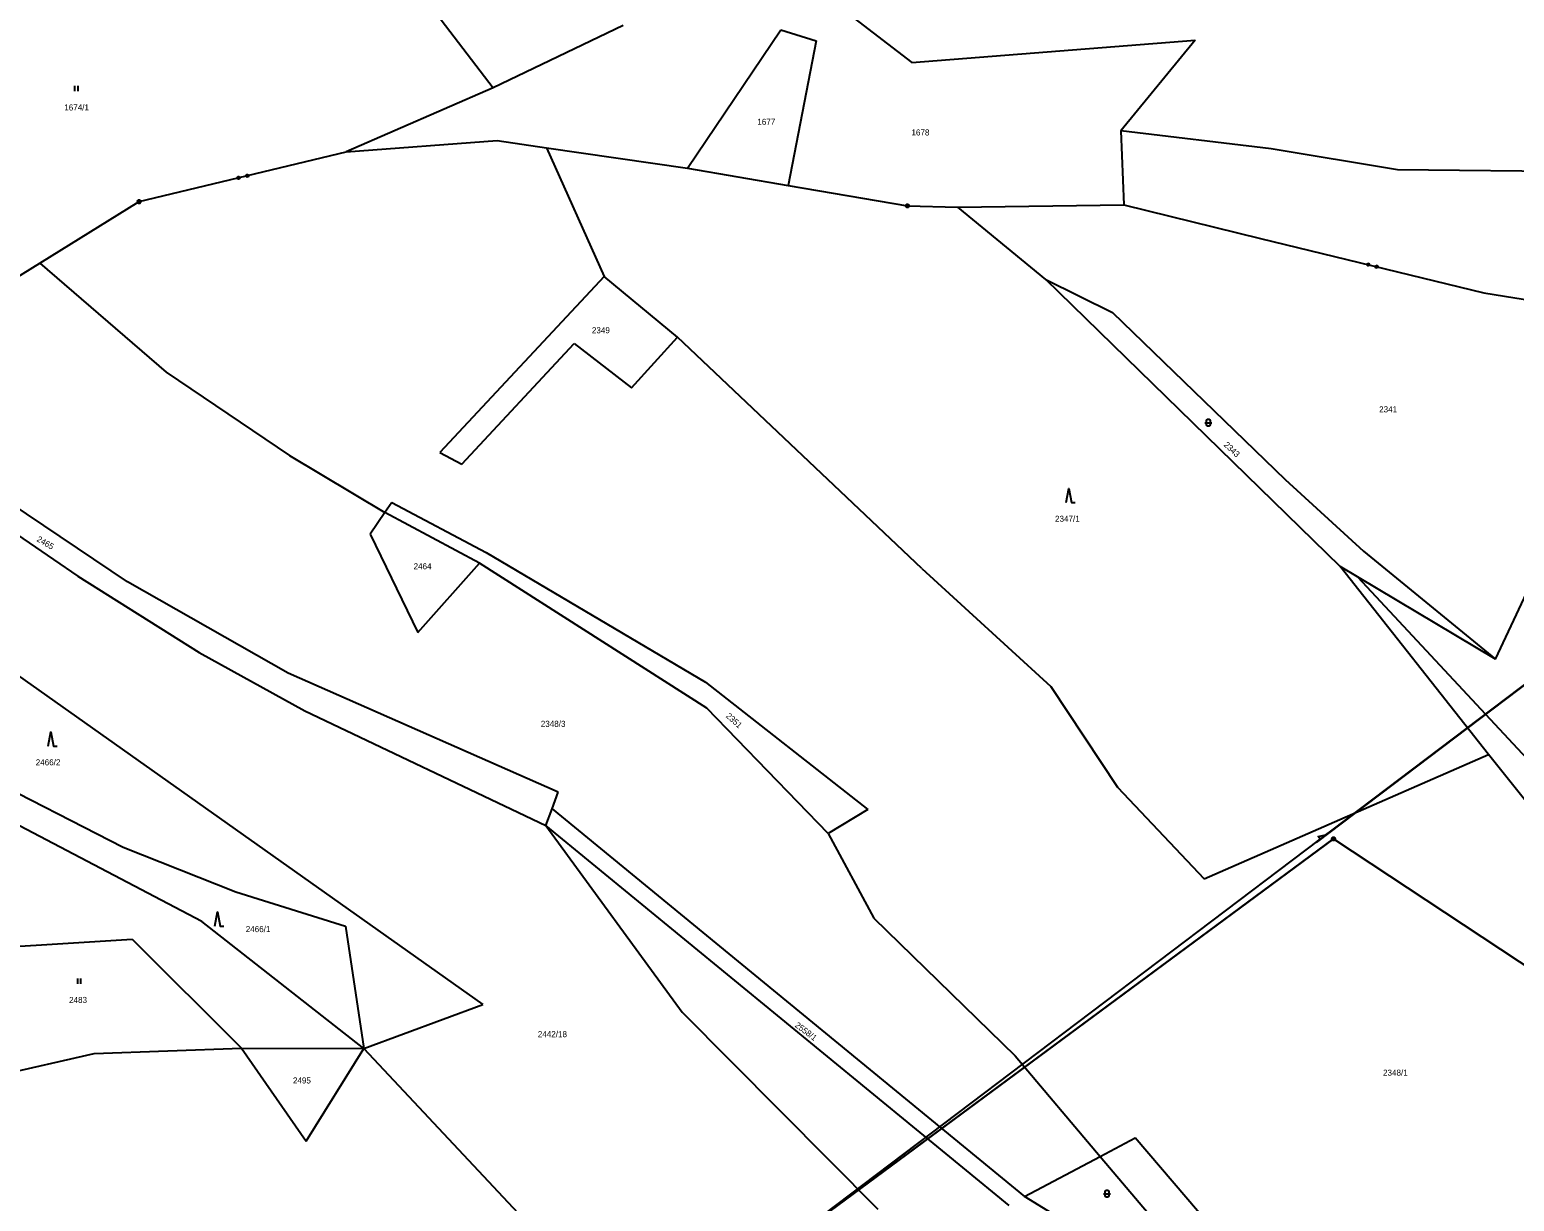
# Model space of a CAD drawing. Extents: x -747792 to -745414, y -1093712 to -1091463.
# Drawn here: x -747200 to -746990.9, y -1092601.7 to -1092436.7 of the extents above; entities that cross this region are included whole.
import ezdxf

# ---------------------------------------------------------------- set-up
doc = ezdxf.new("R2010")
doc.units = 0
for name, color, linetype in [('Pracovní_bod JDTM STC_VC', 7, 'Continuous'), ('Pracovní_bod JDTM STC_VC - číslo', 7, 'Continuous'), ('Pracovní_bod NN - výška', 7, 'Continuous'), ('Pracovní_bod polohopisu - číslo', 7, 'Continuous'), ('Pracovní_bod VN - výška', 7, 'Continuous')]:
    doc.layers.add(name, color=color, linetype=linetype)

msp = doc.modelspace()

# ---------------------------------------------------------------- linework, layer by layer
at = {"layer": 'Pracovní_bod JDTM STC_VC - číslo'}
for points in [[(-747193.73, -1092444.63), (-747193.73, -1092445.38)], [(-747193.23, -1092445.38), (-747193.23, -1092444.63)], [(-747034.52, -1092492.05), (-747033.89, -1092492.05), (-747033.52, -1092492.05)], [(-747054.05, -1092503.3), (-747053.67, -1092501.3), (-747053.3, -1092503.3), (-747052.8, -1092503.3)], [(-747197.44, -1092537.6), (-747197.06, -1092535.6), (-747196.69, -1092537.6), (-747196.19, -1092537.6)], [(-747173.96, -1092562.94), (-747173.59, -1092560.94), (-747173.21, -1092562.94), (-747172.71, -1092562.94)], [(-747193.32, -1092570.31), (-747193.32, -1092571.06)], [(-747192.82, -1092571.06), (-747192.82, -1092570.31)], [(-747048.81, -1092600.62), (-747048.18, -1092600.62), (-747047.81, -1092600.62)]]:
    msp.add_lwpolyline(points, dxfattribs=at)
for points in [[(-747034.27, -1092491.8), (-747034.22, -1092491.66), (-747034.09, -1092491.56), (-747033.94, -1092491.56), (-747033.82, -1092491.66), (-747033.77, -1092491.8), (-747033.77, -1092492.3), (-747033.82, -1092492.45), (-747033.94, -1092492.54), (-747034.09, -1092492.54), (-747034.22, -1092492.45), (-747034.27, -1092492.3)], [(-747048.56, -1092600.37), (-747048.51, -1092600.23), (-747048.39, -1092600.14), (-747048.23, -1092600.14), (-747048.1, -1092600.23), (-747048.06, -1092600.37), (-747048.06, -1092600.87), (-747048.1, -1092601.02), (-747048.23, -1092601.1), (-747048.39, -1092601.1), (-747048.51, -1092601.02), (-747048.56, -1092600.87)]]:
    msp.add_lwpolyline(points, close=True, dxfattribs=at)
at = {"layer": 'Pracovní_bod NN - výška'}
for points in [[(-747095.57, -1092426.1), (-747075.77, -1092441.31)], [(-747146.95, -1092428.88), (-747134.78, -1092444.91)], [(-747116.43, -1092436.11), (-747134.78, -1092444.91)], [(-747107.37, -1092456.22), (-747094.26, -1092436.73)], [(-747094.26, -1092436.73), (-747089.27, -1092438.27)], [(-747089.27, -1092438.27), (-747093.21, -1092458.64)], [(-747075.77, -1092441.31), (-747035.87, -1092438.2)], [(-747035.87, -1092438.2), (-747046.34, -1092450.93)], [(-747134.78, -1092444.91), (-747155.44, -1092453.91)], [(-747046.34, -1092450.93), (-747045.92, -1092461.39)], [(-747025.2, -1092453.5), (-747046.34, -1092450.93)], [(-747155.44, -1092453.91), (-747134.18, -1092452.33)], [(-747134.18, -1092452.33), (-747127.25, -1092453.33)], [(-747127.25, -1092453.33), (-747107.37, -1092456.22)], [(-747127.25, -1092453.33), (-747119.14, -1092471.47)], [(-747007.36, -1092456.44), (-747025.2, -1092453.5)], [(-747184.61, -1092460.92), (-747155.44, -1092453.91)], [(-747170.58, -1092457.38), (-747170.47, -1092457.45), (-747170.44, -1092457.59), (-747170.51, -1092457.7), (-747170.64, -1092457.73), (-747170.75, -1092457.66), (-747170.78, -1092457.53), (-747170.71, -1092457.42), (-747170.58, -1092457.38), (-747170.58, -1092457.41), (-747170.7, -1092457.43), (-747170.73, -1092457.48), (-747170.53, -1092457.43), (-747170.49, -1092457.46), (-747170.76, -1092457.53), (-747170.75, -1092457.57), (-747170.48, -1092457.5), (-747170.47, -1092457.54), (-747170.74, -1092457.61), (-747170.73, -1092457.65), (-747170.46, -1092457.58), (-747170.49, -1092457.63), (-747170.68, -1092457.68), (-747170.63, -1092457.71), (-747170.52, -1092457.68)], [(-747169.37, -1092457.09), (-747169.25, -1092457.16), (-747169.22, -1092457.29), (-747169.29, -1092457.41), (-747169.42, -1092457.44), (-747169.54, -1092457.37), (-747169.57, -1092457.24), (-747169.5, -1092457.12), (-747169.37, -1092457.09), (-747169.38, -1092457.12), (-747169.49, -1092457.14), (-747169.52, -1092457.19), (-747169.33, -1092457.14), (-747169.28, -1092457.17), (-747169.55, -1092457.24), (-747169.54, -1092457.28), (-747169.27, -1092457.21), (-747169.26, -1092457.25), (-747169.53, -1092457.32), (-747169.52, -1092457.36), (-747169.25, -1092457.29), (-747169.28, -1092457.34), (-747169.48, -1092457.39), (-747169.43, -1092457.42), (-747169.31, -1092457.39)], [(-747107.37, -1092456.22), (-747093.21, -1092458.64)], [(-746981.14, -1092456.74), (-747007.36, -1092456.44)], [(-747093.21, -1092458.64), (-747076.39, -1092461.51)], [(-747198.62, -1092469.58), (-747184.61, -1092460.92)], [(-747076.39, -1092461.51), (-747069.3, -1092461.71)], [(-747069.3, -1092461.71), (-747045.92, -1092461.39)], [(-747056.93, -1092471.88), (-747069.3, -1092461.71)], [(-747045.92, -1092461.39), (-747026.66, -1092466.11)], [(-747026.66, -1092466.11), (-746995.22, -1092473.74)], [(-747210.01, -1092476.61), (-747198.62, -1092469.58)], [(-747198.62, -1092469.58), (-747180.81, -1092484.94)], [(-747011.42, -1092469.64), (-747011.35, -1092469.76), (-747011.38, -1092469.89), (-747011.5, -1092469.96), (-747011.63, -1092469.93), (-747011.7, -1092469.81), (-747011.67, -1092469.68), (-747011.55, -1092469.61), (-747011.42, -1092469.64), (-747011.43, -1092469.66), (-747011.55, -1092469.63), (-747011.6, -1092469.66), (-747011.4, -1092469.71), (-747011.37, -1092469.76), (-747011.64, -1092469.69), (-747011.65, -1092469.73), (-747011.38, -1092469.8), (-747011.39, -1092469.84), (-747011.66, -1092469.77), (-747011.67, -1092469.81), (-747011.4, -1092469.87), (-747011.45, -1092469.9), (-747011.64, -1092469.86), (-747011.61, -1092469.91), (-747011.5, -1092469.93)], [(-747010.21, -1092469.94), (-747010.14, -1092470.05), (-747010.17, -1092470.18), (-747010.28, -1092470.25), (-747010.42, -1092470.22), (-747010.49, -1092470.11), (-747010.45, -1092469.98), (-747010.34, -1092469.91), (-747010.21, -1092469.94), (-747010.23, -1092469.95), (-747010.34, -1092469.93), (-747010.39, -1092469.96), (-747010.2, -1092470), (-747010.17, -1092470.05), (-747010.44, -1092469.98), (-747010.45, -1092470.02), (-747010.18, -1092470.09), (-747010.19, -1092470.13), (-747010.46, -1092470.06), (-747010.47, -1092470.1), (-747010.2, -1092470.17), (-747010.24, -1092470.2), (-747010.44, -1092470.15), (-747010.41, -1092470.2), (-747010.29, -1092470.23)], [(-747119.14, -1092471.47), (-747142.29, -1092496.25)], [(-747108.8, -1092480.02), (-747119.14, -1092471.47)], [(-747015.48, -1092512.3), (-747056.93, -1092471.88)], [(-747056.93, -1092471.88), (-747047.53, -1092476.51)], [(-746995.22, -1092473.74), (-746972.76, -1092477.36)], [(-747047.53, -1092476.51), (-747023.2, -1092500.06)], [(-747115.28, -1092487.14), (-747108.8, -1092480.02)], [(-747074.38, -1092512.56), (-747108.8, -1092480.02)], [(-747139.19, -1092497.89), (-747123.35, -1092480.89)], [(-747123.35, -1092480.89), (-747115.28, -1092487.14)], [(-747180.81, -1092484.94), (-747163.45, -1092496.66)], [(-747186.27, -1092514.47), (-747226.54, -1092487.36)], [(-747163.45, -1092496.66), (-747150.01, -1092504.69)], [(-747142.29, -1092496.25), (-747139.19, -1092497.89)], [(-746993.57, -1092525.37), (-746979.63, -1092495.68)], [(-747023.2, -1092500.06), (-747012.15, -1092510.12)], [(-747149.04, -1092503.27), (-747150.01, -1092504.69)], [(-747149.04, -1092503.27), (-747135.76, -1092510.35)], [(-747207, -1092504.27), (-747193.26, -1092513.66)], [(-747150.01, -1092504.69), (-747152.09, -1092507.75)], [(-747136.68, -1092511.85), (-747150.01, -1092504.69)], [(-747152.09, -1092507.75), (-747145.38, -1092521.61)], [(-747145.38, -1092521.61), (-747136.68, -1092511.85)], [(-747104.64, -1092532.25), (-747136.68, -1092511.85)], [(-747135.76, -1092510.35), (-747104.83, -1092528.6)], [(-747012.15, -1092510.12), (-746993.57, -1092525.37)], [(-747193.26, -1092513.66), (-747176.16, -1092524.41)], [(-747074.38, -1092512.56), (-747056.22, -1092529.19)], [(-746994.58, -1092538.79), (-747015.48, -1092512.3)], [(-747013.03, -1092513.76), (-747015.48, -1092512.3)], [(-747013.03, -1092513.76), (-746951.86, -1092579.36)], [(-746993.57, -1092525.37), (-747013.03, -1092513.76)], [(-747163.63, -1092527.3), (-747186.27, -1092514.47)], [(-747207.15, -1092523.79), (-747136.22, -1092573.97)], [(-747176.16, -1092524.41), (-747161.29, -1092532.62)], [(-747175.77, -1092562.31), (-747239.54, -1092528.86)], [(-747125.62, -1092544.1), (-747163.63, -1092527.3)], [(-747104.83, -1092528.6), (-747081.99, -1092546.51)], [(-747056.22, -1092529.19), (-747046.81, -1092543.35)], [(-747161.29, -1092532.62), (-747127.32, -1092548.77)], [(-747087.55, -1092549.91), (-747104.64, -1092532.25)], [(-747034.63, -1092556.29), (-746994.58, -1092538.79)], [(-746969.61, -1092570), (-746994.58, -1092538.79)], [(-747207.26, -1092541.38), (-747186.89, -1092551.84)], [(-747046.81, -1092543.35), (-747034.63, -1092556.29)], [(-747126.46, -1092546.42), (-747125.62, -1092544.1)], [(-747127.32, -1092548.77), (-747126.46, -1092546.42)], [(-747126.46, -1092546.42), (-747059.94, -1092601.01)], [(-747081.99, -1092546.51), (-747087.55, -1092549.91)], [(-747127.32, -1092548.77), (-747108.12, -1092575.08)], [(-747062.09, -1092602.28), (-747127.32, -1092548.77)], [(-747186.89, -1092551.84), (-747170.99, -1092558.13)], [(-747087.55, -1092549.91), (-747081.13, -1092561.8)], [(-747170.99, -1092558.13), (-747155.58, -1092562.96)], [(-747152.98, -1092580.18), (-747175.77, -1092562.31)], [(-747081.13, -1092561.8), (-747061.22, -1092581.21)], [(-747155.58, -1092562.96), (-747152.98, -1092580.18)], [(-747213.49, -1092566.53), (-747185.62, -1092564.79)], [(-747185.62, -1092564.79), (-747170.21, -1092580.13)], [(-747152.98, -1092580.18), (-747136.22, -1092573.97)], [(-747108.12, -1092575.08), (-747080.59, -1092602.79)], [(-747204.55, -1092583.99), (-747190.94, -1092580.88)], [(-747190.94, -1092580.88), (-747170.21, -1092580.13)], [(-747170.21, -1092580.13), (-747161.12, -1092593.23)], [(-747170.21, -1092580.13), (-747152.98, -1092580.18)], [(-747161.12, -1092593.23), (-747152.98, -1092580.18)], [(-747152.98, -1092580.18), (-747125.63, -1092609.32)], [(-747061.22, -1092581.21), (-747049.25, -1092595.36)], [(-747049.25, -1092595.36), (-747044.33, -1092592.76)], [(-747026.5, -1092613.63), (-747044.33, -1092592.76)], [(-747059.94, -1092601.01), (-747049.25, -1092595.36)], [(-747049.25, -1092595.36), (-747028.84, -1092619.47)], [(-747027.96, -1092620.69), (-747059.94, -1092601.01)]]:
    msp.add_lwpolyline(points, dxfattribs=at)
at = {"layer": 'Pracovní_bod polohopisu - číslo'}
for points in [[(-747097.67, -1092610.73), (-746937.26, -1092489.46), (-747018.86, -1092551.15)], [(-747018.66, -1092551), (-747018.27, -1092550.7), (-747018.57, -1092550.3), (-747017.47, -1092550.1), (-747016.27, -1092549.19)], [(-747181.77, -1092672.87), (-747016.39, -1092550.67), (-747100.49, -1092612.81)], [(-747016.47, -1092550.43), (-747016.31, -1092550.43), (-747016.19, -1092550.52), (-747016.14, -1092550.67), (-747016.19, -1092550.81), (-747016.31, -1092550.9), (-747016.47, -1092550.9), (-747016.59, -1092550.81), (-747016.64, -1092550.67), (-747016.59, -1092550.52), (-747016.47, -1092550.43), (-747016.45, -1092550.45), (-747016.33, -1092550.45), (-747016.25, -1092550.49), (-747016.53, -1092550.49), (-747016.57, -1092550.53), (-747016.21, -1092550.53), (-747016.21, -1092550.57), (-747016.57, -1092550.57), (-747016.59, -1092550.61), (-747016.19, -1092550.61), (-747016.17, -1092550.65), (-747016.61, -1092550.65), (-747016.61, -1092550.69), (-747016.17, -1092550.69), (-747016.19, -1092550.73), (-747016.59, -1092550.73), (-747016.58, -1092550.77), (-747016.18, -1092550.77), (-747016.21, -1092550.81), (-747016.57, -1092550.81), (-747016.53, -1092550.85), (-747016.24, -1092550.85), (-747016.3, -1092550.89), (-747016.47, -1092550.89)], [(-747016.39, -1092550.67), (-746945.99, -1092597.19), (-746982.65, -1092572.97)]]:
    msp.add_lwpolyline(points, dxfattribs=at)
at = {"layer": 'Pracovní_bod VN - výška'}
for points in [[(-747184.53, -1092460.68), (-747184.41, -1092460.77), (-747184.36, -1092460.92), (-747184.41, -1092461.06), (-747184.53, -1092461.16), (-747184.69, -1092461.16), (-747184.81, -1092461.06), (-747184.86, -1092460.92), (-747184.81, -1092460.77), (-747184.69, -1092460.68)], [(-747076.32, -1092461.27), (-747076.19, -1092461.36), (-747076.14, -1092461.51), (-747076.19, -1092461.66), (-747076.32, -1092461.75), (-747076.47, -1092461.75), (-747076.59, -1092461.66), (-747076.64, -1092461.51), (-747076.59, -1092461.36), (-747076.47, -1092461.27)]]:
    msp.add_lwpolyline(points, close=True, dxfattribs=at)
for points in [[(-747184.64, -1092460.92), (-747184.58, -1092460.92)], [(-747076.42, -1092461.51), (-747076.36, -1092461.51)]]:
    msp.add_lwpolyline(points, dxfattribs=at)

# ---------------------------------------------------------------- texts
at = {"layer": 'Pracovní_bod JDTM STC_VC'}
for s, p in [('1674/1', (-747195.17, -1092448.08)), ('1677', (-747097.55, -1092450.1)), ('1678', (-747075.84, -1092451.6)), ('2349', (-747120.85, -1092479.45)), ('2341', (-747009.97, -1092490.59)), ('2347/1', (-747055.62, -1092506)), ('2464', (-747145.97, -1092512.7)), ('2348/3', (-747128.05, -1092534.88)), ('2466/2', (-747199.19, -1092540.3)), ('2466/1', (-747169.61, -1092563.79)), ('2483', (-747194.49, -1092573.76)), ('2442/18', (-747128.47, -1092578.58)), ('2348/1', (-747009.42, -1092584)), ('2495', (-747162.96, -1092585.1))]:
    msp.add_text(s, height=0.85, dxfattribs=at).set_placement(p)
for s, rotation, p in [('2343', 316.7311, (-747031.92, -1092495.25)), ('2465', 329.8518, (-747199.13, -1092508.69)), ('2351', 318.1062, (-747102.05, -1092533.46)), ('2558/1', 323.2628, (-747092.34, -1092577.06))]:
    msp.add_text(s, height=0.85, rotation=rotation, dxfattribs=at).set_placement(p)

doc.saveas('drawing.dxf')
